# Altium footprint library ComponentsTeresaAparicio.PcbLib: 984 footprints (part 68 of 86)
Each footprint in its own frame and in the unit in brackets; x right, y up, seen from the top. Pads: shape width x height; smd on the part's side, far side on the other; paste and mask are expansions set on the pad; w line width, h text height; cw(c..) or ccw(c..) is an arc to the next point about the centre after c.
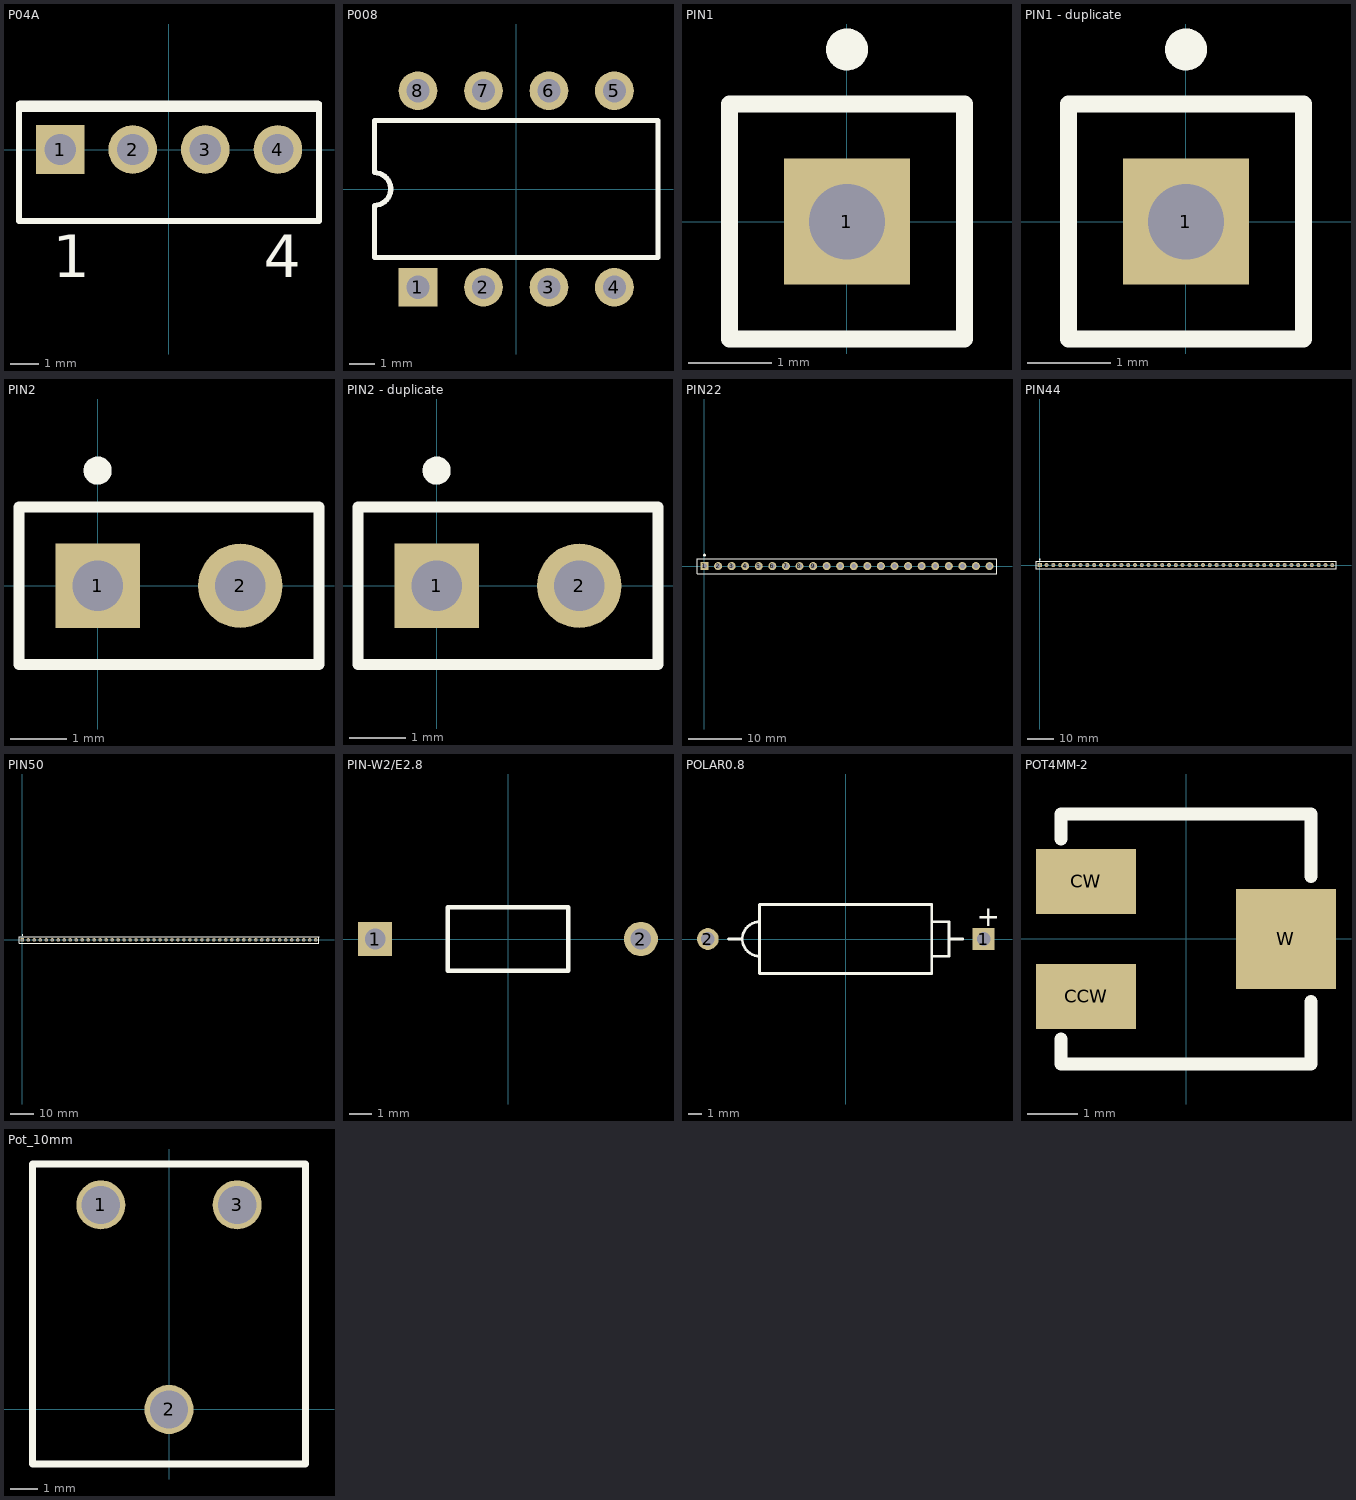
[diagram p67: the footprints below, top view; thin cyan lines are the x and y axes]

## P04A [mm] "TO, Thru-Hole, Vertical, Heatsink Mounted; 4 In-Line Leads; Pitch 2.54 mm"
height 20.6
pads (4):
  rect 1.7x1.7 hole 1.1: 1(-3.81,0)
  round 1.7 hole 1.1: 2(-1.27,0) 3(1.27,0) 4(3.81,0)
Top Overlay:
  rectangle: -5.25,1.311 5.25,1.711
  lines w0.2: -5.25,1.6 -5.25,-2.5 5.25,-2.5 5.25,1.6
  text "4" at 3.31,-4.475 h1.5
  text "1" at -4.06,-4.475 h1.5

## P008 [mm] "DIP; 8 Leads; Row Spacing 7.62 mm; Pitch 2.54 mm"
height 5.08
pads (8):
  rect 1.5x1.5 hole 0.9: 1(-3.81,-3.81)
  round 1.5 hole 0.9: 2(-1.27,-3.81) 3(1.27,-3.81) 4(3.81,-3.81) 5(3.81,3.81) 6(1.27,3.81) 7(-1.27,3.81) 8(-3.81,3.81)
Top Overlay:
  lines w0.2: -5.5,-2.65 -5.5,-0.635 ccw(c-5.5,0) -5.5,0.635 -5.5,2.65 5.5,2.65 5.5,-2.65 -5.5,-2.65
3D body: height 7.11, standoff -0.88, extent -4.953,-3.937 5.207,3.81

## PCBComponent_1 - duplicate [mm]

## PCBComponent_1 - duplicate1 [mm]

## PCBComponent_1 - duplicate2 [mm]

## PIN1 [mm] "Connector; Plug"
pads (1):
  rect 1.5x1.5 hole 0.9: 1(0,0)
Top Overlay:
  circle w0.25: c0,2.05 r0.125
  lines w0.2: -1.4,-1.4 1.4,-1.4 1.4,1.4 -1.4,1.4 -1.4,-1.4

## PIN1 - duplicate [mm] "Generic Antenna; 1 Lead"
pads (1):
  rect 1.5x1.5 hole 0.9: 1(0,0)
Top Overlay:
  circle w0.25: c0,2.05 r0.125
  lines w0.2: -1.4,-1.4 -1.4,1.4 1.4,1.4 1.4,-1.4 -1.4,-1.4

## PIN2 [mm] "Photosensitive Diode; 2 Leads"
pads (2):
  rect 1.5x1.5 hole 0.9: 1(0,0)
  round 1.5 hole 0.9: 2(2.54,0)
Top Overlay:
  circle w0.25: c0,2.05 r0.125
  lines w0.2: -1.4,-1.4 -1.4,1.4 3.94,1.4 3.94,-1.4 -1.4,-1.4

## PIN2 - duplicate [mm] "Photosensitive Diode; 2 Leads"
pads (2):
  rect 1.5x1.5 hole 0.9: 1(0,0)
  round 1.5 hole 0.9: 2(2.54,0)
Top Overlay:
  circle w0.25: c0,2.05 r0.125
  lines w0.2: -1.4,-1.4 -1.4,1.4 3.94,1.4 3.94,-1.4 -1.4,-1.4
3D body: height 7.15, standoff -2.02, extent -3.58,-7.009 6.12,2.691

## PIN22 [mm] "Connector; Edge; 22 Position"
pads (22):
  rect 1.5x1.5 hole 0.9: 1(0,0)
  round 1.5 hole 0.9: 2(2.54,0) 3(5.08,0) 4(7.62,0) 5(10.16,0) 6(12.7,0) 7(15.24,0) 8(17.78,0) 10(22.86,0) 11(25.4,0) 12(27.94,0) 13(30.48,0) 14(33.02,0) 15(35.56,0) 16(38.1,0) 17(40.64,0) 18(43.18,0) 19(45.72,0) 20(48.26,0) 21(50.8,0) 22(53.34,0)
  oval 1.51x1.5 hole 0.9: 9(20.32,0)
Top Overlay:
  circle w0.25: c0,2.05 r0.125
  lines w0.2: -1.4,-1.4 54.74,-1.4 54.74,1.4 -1.4,1.4 -1.4,-1.4

## PIN44 [mm] "Connector; Edge; 44 Position"
pads (44):
  rect 1.5x1.5 hole 0.9: 1(0,0)
  round 1.5 hole 0.9: 2(2.54,0) 3(5.08,0) 4(7.62,0) 5(10.16,0) 6(12.7,0) 7(15.24,0) 8(17.78,0) 10(22.86,0) 11(25.4,0) 12(27.94,0) 13(30.48,0) 14(33.02,0) 15(35.56,0) 16(38.1,0) 17(40.64,0) 18(43.18,0) 19(45.72,0) 20(48.26,0) 21(50.8,0) 22(53.34,0) 23(55.88,0) 24(58.42,0) 25(60.96,0) 26(63.5,0) 27(66.04,0) 28(68.58,0) 29(71.12,0) 30(73.66,0) 31(76.2,0) 32(78.74,0) 33(81.28,0) 34(83.82,0) 35(86.36,0) 36(88.9,0) 37(91.44,0) 38(93.98,0) 39(96.52,0) 40(99.06,0) 41(101.6,0) 42(104.14,0) 43(106.68,0) 44(109.22,0)
  oval 1.51x1.5 hole 0.9: 9(20.32,0)
Top Overlay:
  circle w0.25: c0,2.05 r0.125
  lines w0.2: -1.4,-1.4 -1.4,1.4 110.62,1.4 110.62,-1.4 -1.4,-1.4

## PIN50 [mm] "Connector; Edge; 50 Position"
pads (50):
  rect 1.5x1.5 hole 0.9: 1(0,0)
  round 1.5 hole 0.9: 2(2.54,0) 3(5.08,0) 4(7.62,0) 5(10.16,0) 6(12.7,0) 7(15.24,0) 8(17.78,0) 9(20.32,0) 10(22.86,0) 11(25.4,0) 12(27.94,0) 13(30.48,0) 14(33.02,0) 15(35.56,0) 16(38.1,0) 17(40.64,0) 18(43.18,0) 19(45.72,0) 20(48.26,0) 22(53.34,0) 23(55.88,0) 24(58.42,0) 25(60.96,0) 26(63.5,0) 27(66.04,0) 28(68.58,0) 29(71.12,0) 30(73.66,0) 31(76.2,0) 32(78.74,0) 33(81.28,0) 34(83.82,0) 35(86.36,0) 36(88.9,0) 37(91.44,0) 38(93.98,0) 39(96.52,0) 40(99.06,0) 41(101.6,0) 42(104.14,0) 43(106.68,0) 44(109.22,0) 45(111.76,0) 46(114.3,0) 47(116.84,0) 48(119.38,0) 49(121.92,0) 50(124.46,0)
  oval 1.51x1.5 hole 0.9: 21(50.8,0)
Top Overlay:
  circle w0.25: c0,2.05 r0.125
  lines w0.2: -1.4,-1.4 125.86,-1.4 125.86,1.4 -1.4,1.4 -1.4,-1.4

## PIN-W2/E2.8 [mm] "Thru-Hole; 2 Leads"
pads (2):
  rect 1.5x1.5 hole 0.9: 1(-5.825,0)
  round 1.5 hole 0.9: 2(5.825,0)
Top Overlay:
  lines w0.2: -2.65,-1.4 2.65,-1.4 2.65,1.4 -2.65,1.4 -2.65,-1.4

## POLAR0.8 [mm] "Polarized Capacitor; 2 Leads"
height 5.08
pads (2):
  rect 1.6x1.6 hole 1: 1(10.16,0)
  round 1.6 hole 1: 2(-10.16,0)
Top Overlay:
  lines w0.2: -8.636,0 -7.62,0 ; -6.35,-1.27 cw(c-6.35,0) -6.35,1.27 ; 6.35,-1.27 7.62,-1.27 7.62,1.27 6.35,1.27 ; 7.62,0 8.636,0 ; -6.35,-2.54 -6.35,2.54 6.35,2.54 6.35,-2.54 -6.35,-2.54
  text "+" at 9.652,0.95 h1.5

## POT4MM-2 [mm] "Square Trimming Potentiometer"
pads (3):
  rect 2x1.3 smd: CCW(-2,-1.15) CW(-2,1.15)
  rect 2x2 smd: W(2,0)
Top Overlay:
  lines w0.254: -2.5,-2 -2.5,-2.5 2.5,-2.5 2.5,-1.25 ; -2.5,2 -2.5,2.5 2.5,2.5 2.5,1.25

## Pot_10mm [mm] "Can; 3 Leads; Pin Circle Dia. 2.54 mm; Lead Dia. 0.48 mm (max)"
height 5.33
pads (3):
  round 1.8 hole 1.4: 1(-2.5,7.5) 2(0,0) 3(2.5,7.5)
Top Overlay:
  lines w0.254: -5,-2 -5,-1 -5,9 5,9 5,-2 -5,-2
3D body: height 2.55, standoff -8.35, extent -3.1,1.425 3.4,8.475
